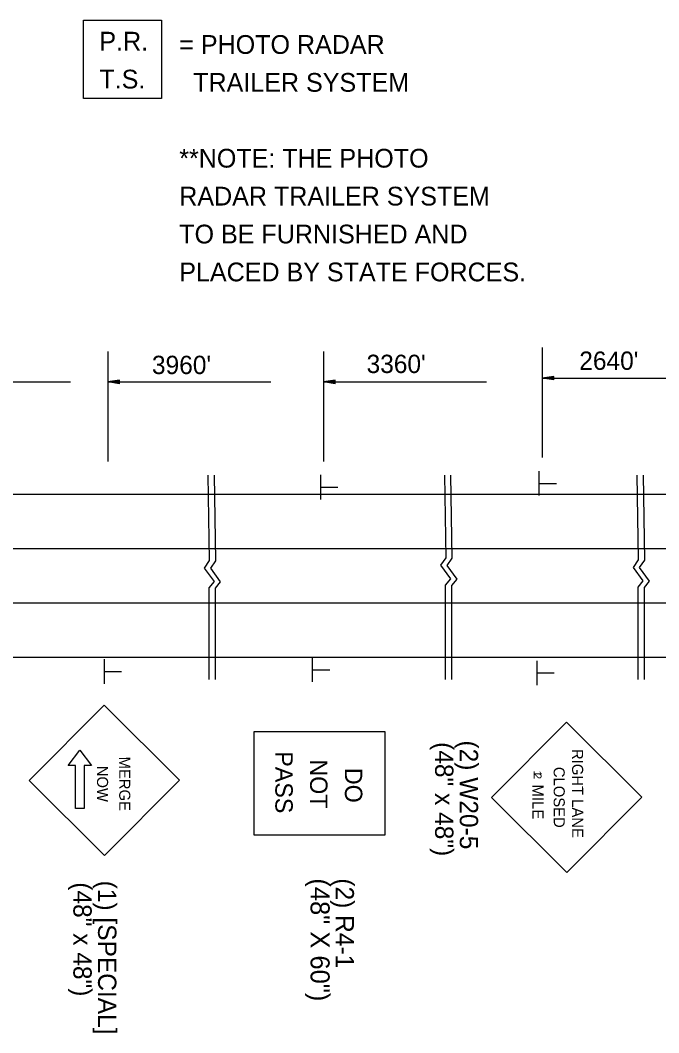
# Model space of a CAD drawing. Extents: x -100 to 745, y -1581 to -107.
# Drawn here: x 211.47 to 231.91, y -312.22 to -279.83 of the extents above; entities that cross this region are included whole.
import ezdxf

# ---------------------------------------------------------------- set-up
doc = ezdxf.new("R2010")
doc.units = 0
doc.layers.add('Default', color=7, linetype='Continuous')

msp = doc.modelspace()

# ---------------------------------------------------------------- linework, layer by layer
at = {"layer": 'Default'}
for p, q in [((214.279, -290.419), (214.279, -293.94)), ((221.18, -290.419), (221.18, -293.94)), ((228.176, -290.299), (228.176, -293.82)), ((228.551, -291.222), (228.176, -291.278)), ((228.551, -291.335), (228.551, -291.222)), ((207.863, -291.398), (213.082, -291.398)), ((214.654, -291.342), (214.279, -291.398)), ((214.279, -291.398), (219.498, -291.398)), ((214.654, -291.455), (214.279, -291.398)), ((214.654, -291.351), (214.342, -291.398)), ((214.654, -291.445), (214.342, -291.398)), ((214.654, -291.361), (214.406, -291.398)), ((214.654, -291.436), (214.406, -291.398)), ((214.654, -291.37), (214.469, -291.398)), ((214.654, -291.426), (214.469, -291.398)), ((214.654, -291.38), (214.532, -291.398)), ((214.654, -291.417), (214.532, -291.398)), ((214.654, -291.39), (214.595, -291.398)), ((214.654, -291.407), (214.595, -291.398)), ((214.654, -291.455), (214.654, -291.342)), ((221.555, -291.342), (221.18, -291.398)), ((221.18, -291.398), (226.398, -291.398)), ((221.555, -291.455), (221.18, -291.398)), ((221.555, -291.351), (221.242, -291.398)), ((221.555, -291.445), (221.242, -291.398)), ((221.555, -291.361), (221.307, -291.398)), ((221.555, -291.436), (221.307, -291.398)), ((221.555, -291.37), (221.369, -291.398)), ((221.555, -291.426), (221.369, -291.398)), ((221.555, -291.38), (221.433, -291.398)), ((221.555, -291.417), (221.433, -291.398)), ((221.555, -291.39), (221.495, -291.398)), ((221.555, -291.407), (221.495, -291.398)), ((221.555, -291.455), (221.555, -291.342)), ((228.176, -291.278), (233.395, -291.278)), ((228.551, -291.335), (228.176, -291.278)), ((228.551, -291.232), (228.239, -291.278)), ((228.551, -291.325), (228.239, -291.278)), ((228.551, -291.241), (228.303, -291.278)), ((228.551, -291.316), (228.303, -291.278)), ((228.551, -291.25), (228.366, -291.278)), ((228.551, -291.306), (228.366, -291.278)), ((228.551, -291.26), (228.429, -291.278)), ((228.551, -291.297), (228.429, -291.278)), ((228.551, -291.27), (228.492, -291.278)), ((228.551, -291.287), (228.492, -291.278)), ((221.089, -295.154), (221.089, -294.372)), ((228.085, -295.034), (228.085, -294.252)), ((221.1, -294.765), (221.634, -294.765)), ((228.097, -294.645), (228.631, -294.645)), ((210.084, -294.99), (216.984, -294.99)), ((216.984, -294.99), (224.378, -294.99)), ((224.378, -294.99), (230.575, -294.99)), ((230.575, -294.99), (236.66, -294.99)), ((210.084, -296.729), (216.984, -296.729)), ((216.984, -296.729), (224.424, -296.729)), ((224.424, -296.729), (230.542, -296.729)), ((230.542, -296.729), (236.66, -296.729)), ((210.084, -298.467), (216.984, -298.467)), ((216.984, -298.467), (224.424, -298.467)), ((224.424, -298.467), (230.542, -298.467)), ((230.542, -298.467), (236.66, -298.467)), ((210.084, -300.206), (216.984, -300.206)), ((214.164, -301.054), (214.164, -300.272)), ((216.984, -300.206), (224.47, -300.206)), ((220.831, -300.998), (220.831, -300.215)), ((224.47, -300.206), (230.508, -300.206)), ((230.508, -300.206), (237.942, -300.206)), ((220.842, -300.609), (221.377, -300.609)), ((228.018, -301.099), (228.018, -300.316)), ((214.176, -300.665), (214.71, -300.665)), ((228.029, -300.709), (228.563, -300.709)), ((211.757, -304.152), (214.158, -301.742)), ((216.566, -304.144), (214.158, -301.742)), ((226.554, -304.696), (228.955, -302.286)), ((231.363, -304.687), (228.955, -302.286)), ((213.007, -303.667), (213.382, -303.18)), ((213.382, -303.18), (213.757, -303.667)), ((213.242, -303.667), (213.007, -303.667)), ((213.242, -305.046), (213.242, -303.667)), ((213.523, -303.667), (213.523, -305.046)), ((213.757, -303.667), (213.523, -303.667)), ((214.167, -306.554), (211.757, -304.152)), ((214.167, -306.554), (216.566, -304.144)), ((228.963, -307.097), (226.554, -304.696)), ((228.963, -307.097), (231.363, -304.687)), ((213.523, -305.046), (213.242, -305.046))]:
    msp.add_line(p, q, dxfattribs=at)
for points in [[(213.497, -282.326), (213.497, -279.826), (215.997, -279.826), (215.997, -282.326)], [(223.145, -305.9), (218.963, -305.9), (218.963, -302.582), (223.145, -302.582)]]:
    msp.add_lwpolyline(points, close=True, dxfattribs=at)
for points in [[(217.479, -294.379), (217.521, -297.11), (217.359, -297.352), (217.675, -297.785), (217.508, -297.985), (217.508, -300.921)], [(217.679, -294.379), (217.721, -297.119), (217.558, -297.36), (217.875, -297.793), (217.708, -297.993), (217.708, -300.921)], [(225.049, -294.379), (225.089, -297.024), (224.927, -297.265), (225.243, -297.698), (225.076, -297.898), (225.076, -300.917)], [(225.248, -294.379), (225.289, -297.032), (225.126, -297.274), (225.443, -297.706), (225.276, -297.906), (225.276, -300.917)], [(231.209, -294.379), (231.25, -297.089), (231.087, -297.331), (231.404, -297.764), (231.237, -297.964), (231.237, -300.917)], [(231.408, -294.379), (231.45, -297.098), (231.287, -297.339), (231.604, -297.772), (231.437, -297.972), (231.437, -300.917)]]:
    msp.add_lwpolyline(points, dxfattribs=at)

# ---------------------------------------------------------------- texts
for s, height, p in [('P.R.', 0.6, (214.006, -280.796)), ('= PHOTO RADAR', 0.6, (216.562, -280.901)), ('T.S.', 0.6, (214.006, -282.009)), ('  TRAILER SYSTEM', 0.6, (216.562, -282.114)), ('**NOTE: THE PHOTO', 0.6, (216.562, -284.54)), ('RADAR TRAILER SYSTEM', 0.6, (216.562, -285.753)), ('TO BE FURNISHED AND', 0.6, (216.562, -286.966)), ('PLACED BY STATE FORCES.', 0.6, (216.562, -288.179)), ("3960'", 0.5862, (215.688, -291.146)), ("3360'", 0.5862, (222.557, -291.113)), ("2640'", 0.5862, (229.365, -291.011))]:
    msp.add_text(s, height=height, dxfattribs=at).set_placement(p)
for s, height, rotation, p in [('(48" x 48")', 0.5862, 270, (224.751, -302.922)), ('(2) W20-5', 0.5862, 270, (225.541, -302.869)), ('RIGHT LANE', 0.3544, 270.1004, (229.133, -303.142)), ('MERGE', 0.3544, 270.1004, (214.638, -303.386)), ('PASS', 0.5566, 270, (219.637, -303.215)), ('NOT', 0.5566, 270, (220.75, -303.474)), ('NOW', 0.3543, 270.1003, (213.929, -303.679)), ('DO', 0.5566, 270, (221.864, -303.746)), ('1', 0.25, 270.0006, (227.906, -303.836)), ('CLOSED', 0.3543, 270.1003, (228.544, -303.714)), ('2', 0.25, 270.0006, (227.906, -303.919)), (' MILE', 0.3567, 270.0006, (227.865, -304.143)), ('(1) [SPECIAL]', 0.5862, 270, (213.963, -307.354)), ('(48" X 60")', 0.61, 270, (220.765, -307.281)), ('(2) R4-1', 0.5862, 270, (221.567, -307.281)), ('(48" x 48")', 0.5862, 270, (213.173, -307.407))]:
    msp.add_text(s, height=height, rotation=rotation, dxfattribs=at).set_placement(p)

doc.saveas('drawing.dxf')
